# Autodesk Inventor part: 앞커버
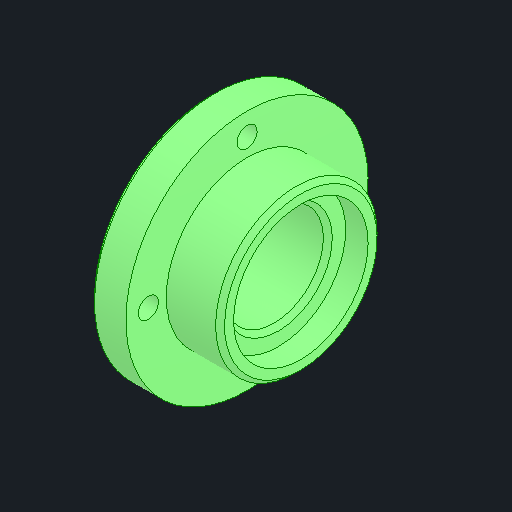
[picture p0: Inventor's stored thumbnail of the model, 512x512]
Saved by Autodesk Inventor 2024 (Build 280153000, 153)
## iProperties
Created: 2025-02
Part Number: 앞커버
Material: 강철, 연강
Document SubType Name: Modeling
Designer: kh_501
Density: 7.85 g/cm^3
Appearance: 기본값
Author: jhkim
Sending System: Autodesk Inventor 2025
Preprocessor: ST-DEVELOPER v20
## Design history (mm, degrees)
node "앞커버1"
node "솔리드2"
node "솔리드1"
